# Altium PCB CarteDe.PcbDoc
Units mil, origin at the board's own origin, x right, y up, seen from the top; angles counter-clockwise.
Board outline 6000 x 4000 mil, 2 copper layers (Top Layer, Bottom Layer); 3 components, 0 nets, 74 pads, 0 vias.
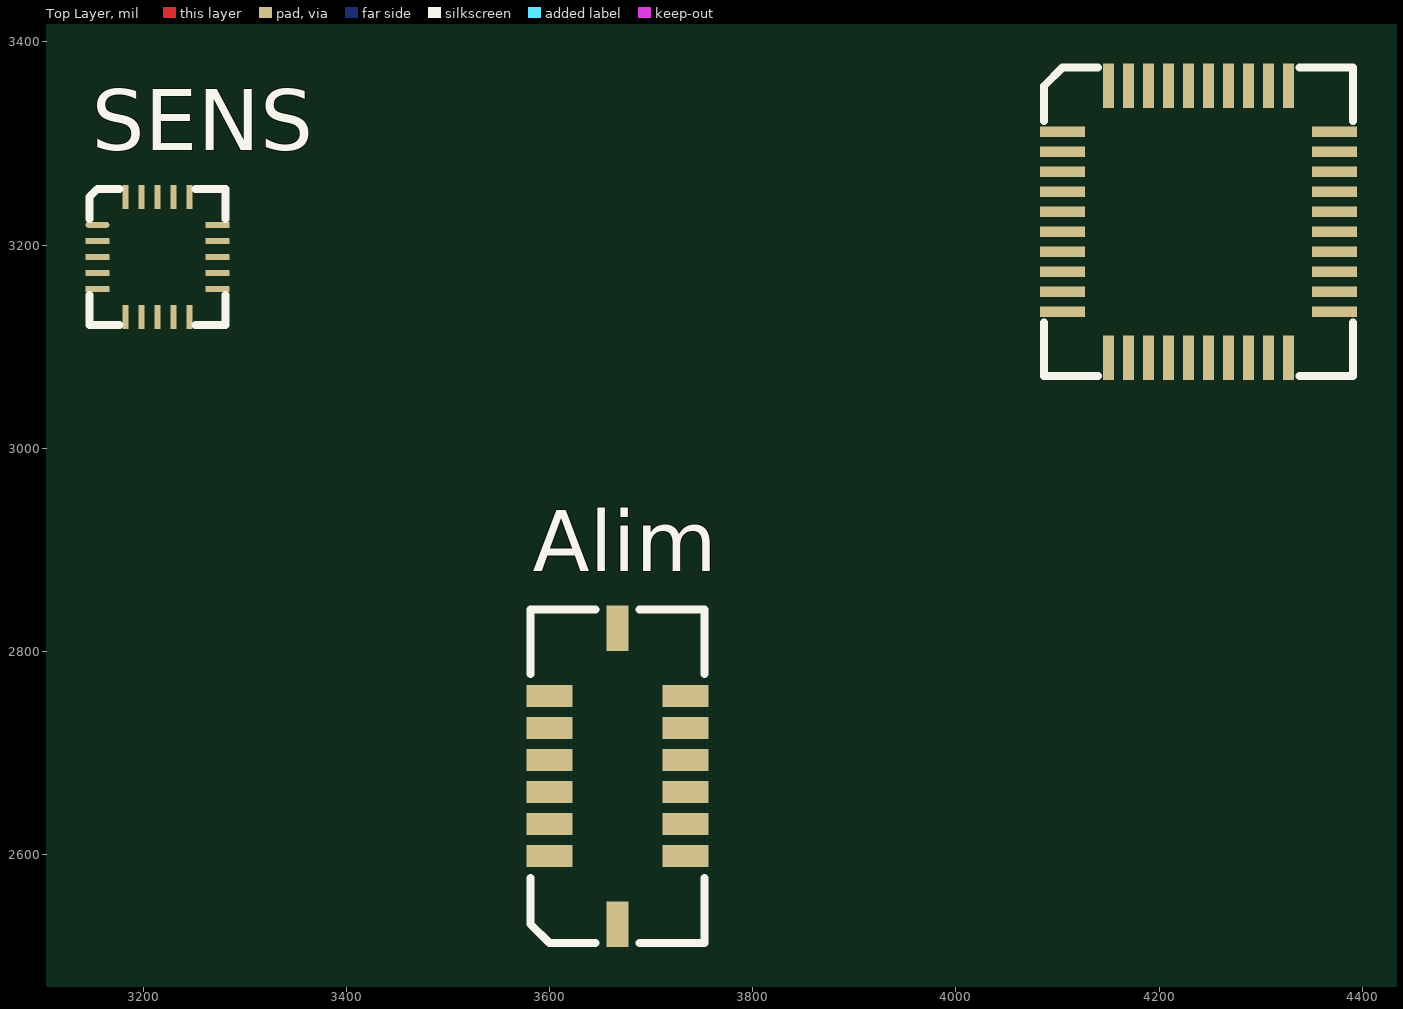
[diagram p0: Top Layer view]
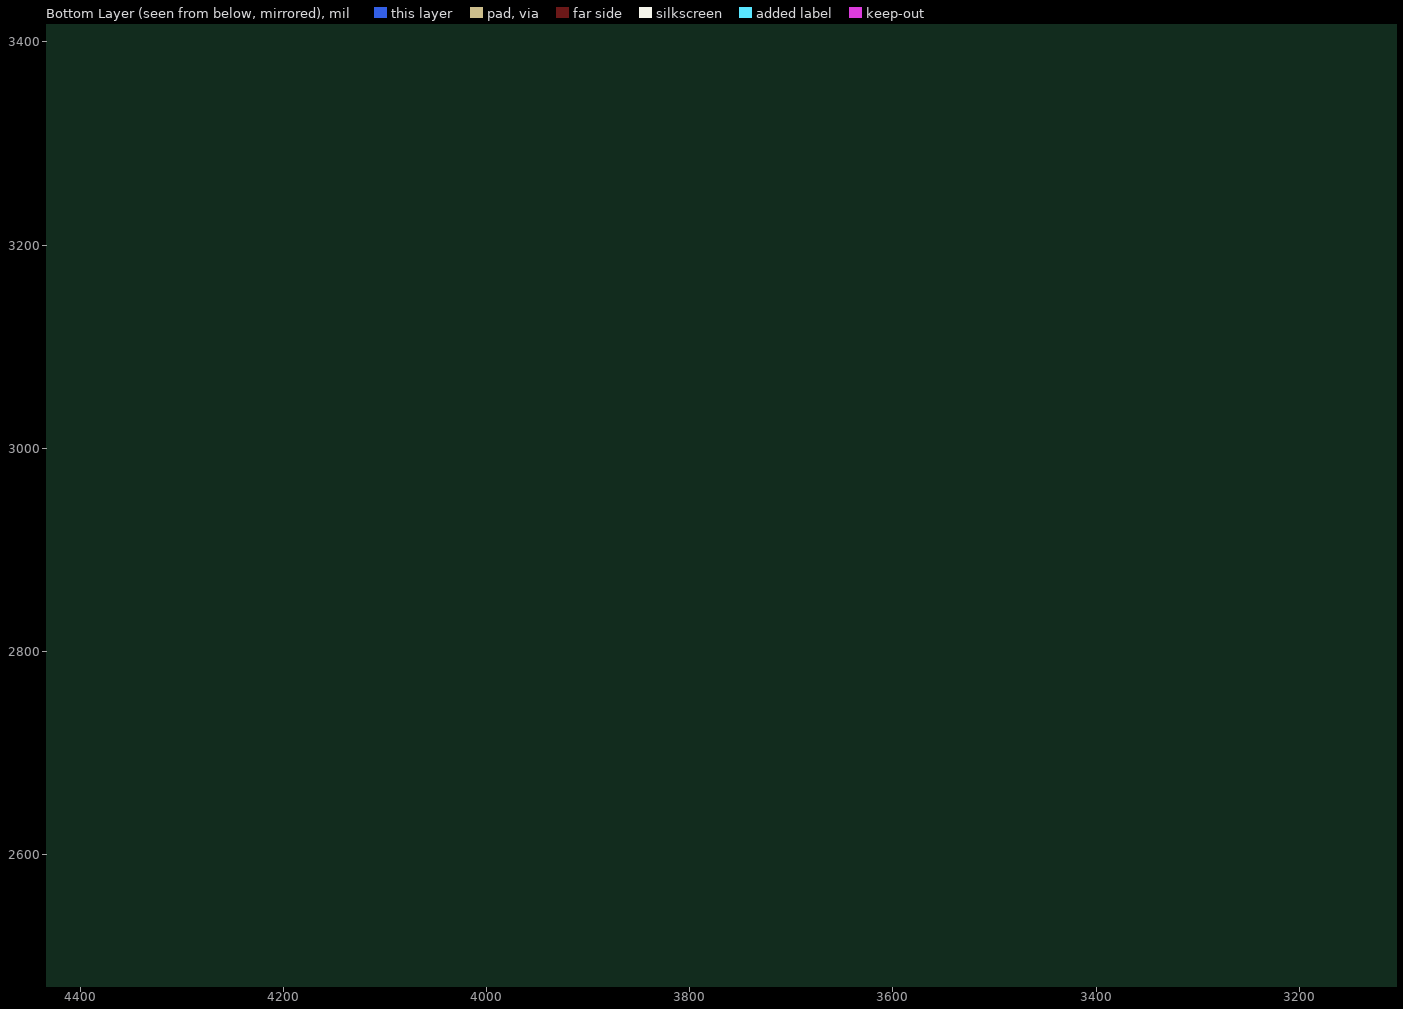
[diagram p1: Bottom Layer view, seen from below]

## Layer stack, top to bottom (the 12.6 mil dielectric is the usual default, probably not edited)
Top Layer: signal copper 1.4
Dielectric: dielectric 12.6, FR-4, Dk 4.8
Bottom Layer: signal copper 1.4

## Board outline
1000,1000 7000,1000 7000,5000 1000,5000

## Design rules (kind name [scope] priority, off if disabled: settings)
Clearance [All] p1: gap=10
PolygonConnect [All] p1: connectstyle=Relief reliefconductorwidth=10 reliefentries=4 polygonreliefangle="90 Angle" airgapwidth=10
RoomDefinition CarteDe [InComponentClass('CarteDe')] p1: confinementstyle=ConfineIn formatcopy=TRUE lockcomponents=FALSE outline 7135,1175 8030,1175 8030,1635 7135,1635
RoutingVias [All] p1: holewidth=28 width=50 viastyle="Through Hole" minholewidth=28 minwidth=50 maxholewidth=28 maxwidth=50
SilkscreenOverComponentPads [All] p1: minsilkscreentomaskgap=10
SolderMaskExpansion [All] p1: expansion=4
Width [All] p1: maxlimit=10 minlimit=10 preferedwidth=10
27 further rules are at their usual default settings.

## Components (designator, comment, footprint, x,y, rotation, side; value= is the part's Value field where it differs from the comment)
* "MBED" LCC40 4105,3311.57 r0 top
Alim "ADXL345" LCC14 3600,2661.57 r90 top
SENS "MPR121" LCC20 3155,3220 r0 top

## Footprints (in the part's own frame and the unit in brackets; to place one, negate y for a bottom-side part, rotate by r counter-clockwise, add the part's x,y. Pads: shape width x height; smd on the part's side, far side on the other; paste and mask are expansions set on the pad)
LCC14 [mm]
  rect 0.55x1.145 smd: 1(0,0) 2(-0.8,0) 3(-1.6,0) 5(-1.6,-3.4) 6(-0.8,-3.4) 7(0,-3.4) 8(0.8,-3.4) 9(1.6,-3.4) 10(2.4,-3.4) 12(2.4,0) 13(1.6,0) 14(0.8,0)
  rect 1.145x0.55 smd: 4(-3.3,-1.7) 11(4.1,-1.7)
  silkscreen extent -3.77,-3.87 4.57,0.47
LCC20 [mm]
  oval 0.6x0.15 smd: 1(0,0)
  rect 0.6x0.15 smd: 2(0,-0.4) 3(0,-0.8) 4(0,-1.2) 5(0,-1.6) 11(3,-1.6) 12(3,-1.2) 13(3,-0.8) 14(3,-0.4) 15(3,0)
  rect 0.15x0.6 smd: 6(0.7,-2.3) 7(1.1,-2.3) 8(1.5,-2.3) 9(1.9,-2.3) 10(2.3,-2.3) 16(2.3,0.7) 17(1.9,0.7) 18(1.5,0.7) 19(1.1,0.7) 20(0.7,0.7)
  silkscreen extent -0.2,-2.5 3.2,0.9
LCC40 [mm]
  rect 1.12x0.27 smd: 1(0,0) 2(0,-0.5) 3(0,-1) 4(0,-1.5) 5(0,-2) 6(0,-2.5) 7(0,-3) 8(0,-3.5) 9(0,-4) 10(0,-4.5) 21(6.8,-4.5) 22(6.8,-4) 23(6.8,-3.5) 24(6.8,-3) 25(6.8,-2.5) 26(6.8,-2) 27(6.8,-1.5) 28(6.8,-1) 29(6.8,-0.5) 30(6.8,0)
  rect 0.27x1.12 smd: 11(1.15,-5.65) 12(1.65,-5.65) 13(2.15,-5.65) 14(2.65,-5.65) 15(3.15,-5.65) 16(3.65,-5.65) 17(4.15,-5.65) 18(4.65,-5.65) 19(5.15,-5.65) 20(5.65,-5.65) 31(5.65,1.15) 32(5.15,1.15) 33(4.65,1.15) 34(4.15,1.15) 35(3.65,1.15) 36(3.15,1.15) 37(2.65,1.15) 38(2.15,1.15) 39(1.65,1.15) 40(1.15,1.15)
  silkscreen extent -0.46,-6.11 7.26,1.61

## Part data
Alim: "Alimentation ADXL345"
SENS: "Touch sensor"

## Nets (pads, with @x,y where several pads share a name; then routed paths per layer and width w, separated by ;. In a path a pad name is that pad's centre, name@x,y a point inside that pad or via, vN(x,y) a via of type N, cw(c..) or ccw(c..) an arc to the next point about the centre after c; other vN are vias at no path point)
pads on no net: *.1 *.2 *.3 *.4 *.5 *.6 *.7 *.8 *.9 *.10 *.11 *.12 *.13 *.14 *.15 *.16 *.17 *.18 *.19 *.20 *.21 *.22 *.23 *.24 *.25 *.26 *.27 *.28 *.29 *.30 *.31 *.32 *.33 *.34 *.35 *.36 *.37 *.38 *.39 *.40 Alim.1 Alim.2 Alim.3 Alim.4 Alim.5 Alim.6 Alim.7 Alim.8 Alim.9 Alim.10 Alim.11 Alim.12 Alim.13 Alim.14 SENS.1 SENS.2 SENS.3 SENS.4 SENS.5 SENS.6 SENS.7 SENS.8 SENS.9 SENS.10 SENS.11 SENS.12 SENS.13 SENS.14 SENS.15 SENS.16 SENS.17 SENS.18 SENS.19 SENS.20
